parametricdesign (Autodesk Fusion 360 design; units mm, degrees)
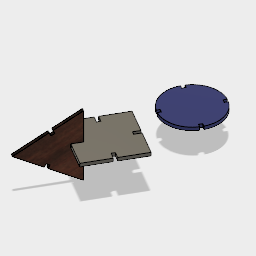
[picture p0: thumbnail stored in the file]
parameter "lengthofobject" = 100
parameter "widthofobject" = 100
parameter "heightofmaterial" = 6
parameter "depthofmaterial" = 12
parameter "radiusofcircle" = 50
sketch "Sketch1" plane through (0, 0, 0) normal (0, 1, 0) x axis (1, 0, 0)
  line L1 (-50, -50) -> (50, -50)
  line L2 (-50, 50) -> (-50, -50)
  line L3 (50, 50) -> (-50, 50)
  line L4 (50, -50) -> (50, 50)
  line L5 (-50, 50) -> (50, -50)
  line L6 (50, 50) -> (-50, -50)
  dimension "d1" distance L1 L3 = 100 (= "lengthofobject")
  dimension "d7" distance L2 L4 = 100 (= "widthofobject")
extrude "Extrude1" new body sketch "Sketch1" profile of L1 L2 L3 L4 along normal blind 6 (= "heightofmaterial")
sketch "Sketch2" plane through (0, 0, 50) normal (0, 0, 1) x axis (1, 0, 0)
  line L1 (50, 0) -> (-50, 0)
  line L2 (50, 6) -> (50, 0)
  line L3 (-50, 6) -> (50, 6)
  line L4 (-50, 0) -> (-50, 6)
  line L5 (-3, 0) -> (3, 0)
  line L6 (-3, 6) -> (-3, 0)
  line L7 (3, 6) -> (-3, 6)
  line L8 (3, 0) -> (3, 6)
  line L9 (-3, 6) -> (3, 0)
  line L10 (3, 6) -> (-3, 0)
  dimension "d10" distance L6 L8 = 6 (= "heightofmaterial")
  dimension "d11" distance L5 L7 = 6 (= "heightofmaterial")
  dimension "d23" distance L4 L6 = 47 (= "widthofobject / 2 - heightofmaterial / 2")
extrude "Extrude2" cut sketch "Sketch2" profile of L1 L3 L5 L6 L7 L8 no distance stored
sketch "Sketch3" plane through (50, 0, 0) normal (1, 0, 0) x axis (0, 0, -1)
  line L1 (50, 0) -> (-50, 0)
  line L2 (50, 6) -> (50, 0)
  line L3 (-50, 6) -> (50, 6)
  line L4 (-50, 0) -> (-50, 6)
  line L5 (-3, 6) -> (3, 6)
  line L6 (-3, 0) -> (-3, 6)
  line L7 (3, 0) -> (-3, 0)
  line L8 (3, 6) -> (3, 0)
  line L9 (-3, 0) -> (3, 6)
  line L10 (3, 0) -> (-3, 6)
  dimension "d14" distance L6 L8 = 6 (= "heightofmaterial")
  dimension "d15" distance L5 L7 = 6 (= "heightofmaterial")
  dimension "d24" distance L4 L6 = 47 (= "widthofobject / 2 - heightofmaterial / 2")
extrude "Extrude3" cut sketch "Sketch3" profile of L1 L3 L5 L6 L7 L8 no distance stored
sketch "Sketch4" plane through (0, 0, -50) normal (0, 0, -1) x axis (-1, 0, 0)
  line L1 (50, 0) -> (-50, 0)
  line L2 (50, 6) -> (50, 0)
  line L3 (-50, 6) -> (50, 6)
  line L4 (-50, 0) -> (-50, 6)
  line L5 (-3, 0) -> (3, 0)
  line L6 (-3, 6) -> (-3, 0)
  line L7 (3, 6) -> (-3, 6)
  line L8 (3, 0) -> (3, 6)
  line L9 (-3, 6) -> (3, 0)
  line L10 (3, 6) -> (-3, 0)
  dimension "d18" distance L6 L8 = 6 (= "heightofmaterial")
  dimension "d19" distance L5 L7 = 6 (= "heightofmaterial")
  dimension "d20" distance L4 L6 = 47 (= "widthofobject / 2 - heightofmaterial / 2")
extrude "Extrude4" cut sketch "Sketch4" profile of L1 L3 L5 L6 L7 L8 no distance stored
sketch "Sketch5" plane through (-50, 0, 0) normal (-1, 0, 0) x axis (0, 0, 1)
  line L1 (50, 0) -> (-50, 0)
  line L2 (50, 6) -> (50, 0)
  line L3 (-50, 6) -> (50, 6)
  line L4 (-50, 0) -> (-50, 6)
  line L5 (-3, 0) -> (3, 0)
  line L6 (-3, 6) -> (-3, 0)
  line L7 (3, 6) -> (-3, 6)
  line L8 (3, 0) -> (3, 6)
  line L9 (-3, 6) -> (3, 0)
  line L10 (3, 6) -> (-3, 0)
  point P1 (0, 0)
  dimension "d25" distance P1 L7 = 6 (= "heightofmaterial")
  dimension "d26" distance L6 L8 = 6 (= "heightofmaterial")
  dimension "d27" distance L4 L6 = 47 (= "widthofobject / 2 - heightofmaterial / 2")
extrude "Extrude5" cut sketch "Sketch5" profile of L1 L3 L5 L6 L7 L8 no distance stored
sketch "Sketch6" plane through (0, 0, 0) normal (0, 1, 0) x axis (1, 0, 0)
  circle C1 centre (200, 0) radius 50
  dimension "d30" diameter C1 = 100 (= "radiusofcircle * 2")
extrude "Extrude6" sketch "Sketch6" blind 6 (= "heightofmaterial")
sketch "Sketch7" plane through (0, 6, 0) normal (0, 1, 0) x axis (-1, 0, 0)
  line L1 (-197, 56) -> (-203, 56)
  line L2 (-197, 44) -> (-197, 56)
  line L3 (-203, 44) -> (-197, 44)
  line L4 (-203, 56) -> (-203, 44)
  line L5 (-197, 44) -> (-203, 56)
  line L6 (-203, 44) -> (-197, 56)
  circle C1 centre (-200, 0) radius 50
  point P2 (-200, 0)
  dimension "d33" distance P2 L3 = 44 (= "radiusofcircle - depthofmaterial / 2")
  dimension "d34" distance L2 L4 = 6 (= "heightofmaterial")
  dimension "d35" distance L1 L3 = 12 (= "depthofmaterial")
extrude "Extrude7" sketch "Sketch7" profile of C1 L2 L3 L4 no distance stored
sketch "Sketch8" plane through (0, 6, 0) normal (0, 1, 0) x axis (-1, 0, 0)
  line L1 (-203, 49.9099) -> (-203, 44)
  line L2 (-197, 44) -> (-197, 49.9099)
  line L3 (-203, 44) -> (-197, 44)
  line L4 (-244, 3) -> (-256, 3)
  line L5 (-244, -3) -> (-244, 3)
  line L6 (-256, -3) -> (-244, -3)
  line L7 (-256, 3) -> (-256, -3)
  line L8 (-244, -3) -> (-256, 3)
  line L9 (-256, -3) -> (-244, 3)
  arc A1 centre (-200, 0) radius 50 clockwise from (-197, 49.9099) to (-203, 49.9099)
  point P5 (-200, 0)
  dimension "d38" distance L5 L7 = 12 (= "depthofmaterial")
  dimension "d39" distance L4 L6 = 6 (= "heightofmaterial")
  dimension "d40" distance P5 L5 = 44 (= "radiusofcircle - depthofmaterial / 2")
extrude "Extrude8" cut sketch "Sketch8" profile of A1 L4 L5 L6 no distance stored
sketch "Sketch9" plane through (0, 6, 0) normal (0, 1, 0) x axis (-1, 0, 0)
  line L1 (-244, 3) -> (-249.9099, 3)
  line L2 (-244, -3) -> (-244, 3)
  line L3 (-249.9099, -3) -> (-244, -3)
  line L4 (-197, 44) -> (-197, 49.9099)
  line L5 (-203, 44) -> (-197, 44)
  line L6 (-203, 49.9099) -> (-203, 44)
  line L7 (-197, -44) -> (-203, -44)
  line L8 (-197, -56) -> (-197, -44)
  line L9 (-203, -56) -> (-197, -56)
  line L10 (-203, -44) -> (-203, -56)
  line L11 (-197, -56) -> (-203, -44)
  line L12 (-203, -56) -> (-197, -44)
  arc A1 centre (-200, 0) radius 50 clockwise from (-197, 49.9099) to (-249.9099, -3)
  arc A2 centre (-200, 0) radius 50 clockwise from (-249.9099, 3) to (-203, 49.9099)
  point P7 (-200, 0)
  dimension "d43" distance L7 L9 = 12 (= "depthofmaterial")
  dimension "d44" distance P7 L7 = 44 (= "radiusofcircle - depthofmaterial / 2")
  dimension "d45" distance L8 L10 = 6 (= "heightofmaterial")
extrude "Extrude9" sketch "Sketch9" profile of A1 L7 L8 L10 no distance stored
sketch "Sketch10" plane through (0, 6, 0) normal (0, 1, 0) x axis (-1, 0, 0)
  line L1 (-197, -49.9099) -> (-197, -44)
  line L2 (-197, 44) -> (-197, 49.9099)
  line L3 (-203, 44) -> (-197, 44)
  line L4 (-203, 49.9099) -> (-203, 44)
  line L5 (-244, 3) -> (-249.9099, 3)
  line L6 (-244, -3) -> (-244, 3)
  line L7 (-249.9099, -3) -> (-244, -3)
  line L8 (-203, -44) -> (-203, -49.9099)
  line L9 (-197, -44) -> (-203, -44)
  line L10 (-144, 3) -> (-156, 3)
  line L11 (-144, -3) -> (-144, 3)
  line L12 (-156, -3) -> (-144, -3)
  line L13 (-156, 3) -> (-156, -3)
  line L14 (-144, -3) -> (-156, 3)
  line L15 (-156, -3) -> (-144, 3)
  arc A1 centre (-200, 0) radius 50 clockwise from (-197, 49.9099) to (-197, -49.9099)
  arc A2 centre (-200, 0) radius 50 clockwise from (-249.9099, 3) to (-203, 49.9099)
  arc A3 centre (-200, 0) radius 50 clockwise from (-203, -49.9099) to (-249.9099, -3)
  point P5 (-200, 0)
  dimension "d48" distance P5 L13 = 44 (= "radiusofcircle - depthofmaterial / 2")
  dimension "d49" distance L10 L12 = 6 (= "heightofmaterial")
extrude "Extrude10" sketch "Sketch10" profile of A1 L10 L12 L13 no distance stored
sketch "Sketch11" plane through (0, 0, 0) normal (0, 1, 0) x axis (1, 0, 0)
  line L1 (57.735, -220) -> (0, -120)
  line L2 (115.4701, -120) -> (57.735, -220)
  line L3 (0, -120) -> (115.4701, -120)
  point P2 (0, -120)
  point P3 (57.735, -220)
  dimension "d52" distance P2 P3 = 100 (= "lengthofobject")
  dimension "d53" distance P2 L2 = 100 (= "lengthofobject")
extrude "Extrude11" sketch "Sketch11" blind 6 (= "heightofmaterial")
sketch "Sketch12" plane through (0, 6, 0) normal (0, 1, 0) x axis (-1, 0, 0)
  line L1 (0, 120) -> (-115.4701, 120)
  line L2 (-57.735, 220) -> (0, 120)
  line L3 (-115.4701, 120) -> (-57.735, 220)
  line L4 (-89.6025, 164.8038) -> (-86.6025, 170)
  line L5 (-84.4064, 161.8038) -> (-89.6025, 164.8038)
  line L6 (-81.4064, 167) -> (-84.4064, 161.8038)
  line L7 (-86.6025, 170) -> (-81.4064, 167)
  dimension "d56" distance L5 L7 = 6 (= "heightofmaterial")
  dimension "d57" distance L4 L6 = 6 (= "depthofmaterial / 2")
extrude "Extrude12" sketch "Sketch12" profile of L3 L4 L5 L6 L7 no distance stored
sketch "Sketch13" plane through (0, 6, 0) normal (0, 1, 0) x axis (-1, 0, 0)
  line L1 (-89.6025, 164.8038) -> (-84.4064, 161.8038)
  line L2 (-115.4701, 120) -> (-89.6025, 164.8038)
  line L3 (0, 120) -> (-115.4701, 120)
  line L4 (-57.735, 220) -> (0, 120)
  line L5 (-86.6025, 170) -> (-57.735, 220)
  line L6 (-81.4064, 167) -> (-86.6025, 170)
  line L7 (-84.4064, 161.8038) -> (-81.4064, 167)
  line L8 (-59.4701, 126) -> (-65.4701, 126)
  line L9 (-59.4701, 114) -> (-59.4701, 126)
  line L10 (-65.4701, 114) -> (-59.4701, 114)
  line L11 (-65.4701, 126) -> (-65.4701, 114)
  line L12 (-59.4701, 114) -> (-65.4701, 126)
  line L13 (-65.4701, 114) -> (-59.4701, 126)
  point P4 (-115.4701, 120)
  dimension "d60" distance L9 L11 = 6 (= "heightofmaterial")
  dimension "d61" distance P4 L11 = 50 (= "lengthofobject / 2")
  dimension "d62" distance L8 L10 = 12 (= "depthofmaterial")
extrude "Extrude13" sketch "Sketch13" profile of L3 L8 L9 L11 no distance stored
sketch "Sketch14" plane through (0, 6, 0) normal (0, 1, 0) x axis (-1, 0, 0)
  line L1 (-65.4701, 126) -> (-65.4701, 120)
  line L2 (-59.4701, 126) -> (-65.4701, 126)
  line L3 (-59.4701, 120) -> (-59.4701, 126)
  line L4 (0, 120) -> (-59.4701, 120)
  line L5 (-57.735, 220) -> (0, 120)
  line L6 (-86.6025, 170) -> (-57.735, 220)
  line L7 (-81.4064, 167) -> (-86.6025, 170)
  line L8 (-84.4064, 161.8038) -> (-81.4064, 167)
  line L9 (-89.6025, 164.8038) -> (-84.4064, 161.8038)
  line L10 (-115.4701, 120) -> (-89.6025, 164.8038)
  line L11 (-65.4701, 120) -> (-115.4701, 120)
  line L12 (-25.8675, 164.8038) -> (-28.8675, 170)
  line L13 (-31.0637, 161.8038) -> (-25.8675, 164.8038)
  line L14 (-34.0637, 167) -> (-31.0637, 161.8038)
  line L15 (-28.8675, 170) -> (-34.0637, 167)
  dimension "d65" distance L13 L15 = 6 (= "heightofmaterial")
  dimension "d66" distance L12 L14 = 6 (= "depthofmaterial / 2")
extrude "Extrude14" sketch "Sketch14" profile of L5 L12 L13 L14 L15 no distance stored
align "Align1"
align "Align2"
move "Move1"
move "Move2"
move "Move3"
move "Move4"
move "Move5"
sketch "Sketch15" plane through (0, -65.0126, 0) normal (0, 1, 0) x axis (-1, 0, 0)
  line L1 (-240.9709, -10.5559) -> (-238.0159, -5.4377)
  line L2 (-182.0089, 9.5693) -> (-176.8907, 6.6144)
  line L3 (-179.0089, 14.7655) -> (-182.0089, 9.5693)
  line L4 (-173.8907, 11.8105) -> (-179.0089, 14.7655)
  line L5 (-194.0159, 70.7725) -> (-191.0609, 75.8907)
  line L6 (-199.2121, 73.7725) -> (-194.0159, 70.7725)
  line L7 (-196.2571, 78.8907) -> (-199.2121, 73.7725)
  line L8 (-255.2191, 58.7655) -> (-260.3372, 61.7205)
  line L9 (-258.2191, 53.5693) -> (-255.2191, 58.7655)
  line L10 (-263.3372, 56.5243) -> (-258.2191, 53.5693)
  line L11 (-243.2121, -2.4377) -> (-246.167, -7.5559)
  line L12 (-238.0159, -5.4377) -> (-243.2121, -2.4377)
  line L13 (-238.0159, -5.4377) -> (-240.9709, -10.5559)
  line L14 (-243.2121, -2.4377) -> (-238.0159, -5.4377)
  line L15 (-246.167, -7.5559) -> (-243.2121, -2.4377)
  line L16 (-258.2191, 53.5693) -> (-263.3372, 56.5243)
  line L17 (-255.2191, 58.7655) -> (-258.2191, 53.5693)
  line L18 (-260.3372, 61.7205) -> (-255.2191, 58.7655)
  line L19 (-199.2121, 73.7725) -> (-196.2571, 78.8907)
  line L20 (-194.0159, 70.7725) -> (-199.2121, 73.7725)
  line L21 (-191.0609, 75.8907) -> (-194.0159, 70.7725)
  line L22 (-179.0089, 14.7655) -> (-173.8907, 11.8105)
  line L23 (-182.0089, 9.5693) -> (-179.0089, 14.7655)
  line L24 (-176.8907, 6.6144) -> (-182.0089, 9.5693)
  arc A1 centre (-218.614, 34.1674) radius 50 clockwise from (-176.8907, 6.6144) to (-240.9709, -10.5559)
  arc A2 centre (-218.614, 34.1674) radius 50 clockwise from (-191.0609, 75.8907) to (-173.8907, 11.8105)
  arc A3 centre (-218.614, 34.1674) radius 50 clockwise from (-260.3372, 61.7205) to (-196.2571, 78.8907)
  arc A4 centre (-218.614, 34.1674) radius 50 clockwise from (-246.167, -7.5559) to (-263.3372, 56.5243)
  arc A5 centre (-218.614, 34.1674) radius 50 clockwise from (-246.167, -7.5559) to (-263.3372, 56.5243)
  arc A6 centre (-218.614, 34.1674) radius 50 clockwise from (-260.3372, 61.7205) to (-196.2571, 78.8907)
  arc A7 centre (-218.614, 34.1674) radius 50 clockwise from (-191.0609, 75.8907) to (-173.8907, 11.8105)
  arc A8 centre (-218.614, 34.1674) radius 50 clockwise from (-176.8907, 6.6144) to (-240.9709, -10.5559)
sketch "Sketch16" plane through (0, -49, 0) normal (0, 1, 0) x axis (-1, 0, 0)
  line L1 (-182.4013, 216.0718) -> (-176.4013, 226.4641)
  line L2 (-187.5974, 219.0718) -> (-182.4013, 216.0718)
  line L3 (-181.5974, 229.4641) -> (-187.5974, 219.0718)
  line L4 (-222.3006, 252.9641) -> (-181.5974, 229.4641)
  line L5 (-245.8006, 212.2609) -> (-222.3006, 252.9641)
  line L6 (-235.4083, 206.2609) -> (-245.8006, 212.2609)
  line L7 (-238.4083, 201.0648) -> (-235.4083, 206.2609)
  line L8 (-248.8006, 207.0648) -> (-238.4083, 201.0648)
  line L9 (-272.3006, 166.3616) -> (-248.8006, 207.0648)
  line L10 (-231.5974, 142.8616) -> (-272.3006, 166.3616)
  line L11 (-225.5974, 153.2539) -> (-231.5974, 142.8616)
  line L12 (-220.4013, 150.2539) -> (-225.5974, 153.2539)
  line L13 (-226.4013, 139.8616) -> (-220.4013, 150.2539)
  line L14 (-185.6981, 116.3616) -> (-226.4013, 139.8616)
  line L15 (-162.1981, 157.0648) -> (-185.6981, 116.3616)
  line L16 (-172.5904, 163.0648) -> (-162.1981, 157.0648)
  line L17 (-169.5904, 168.2609) -> (-172.5904, 163.0648)
  line L18 (-159.1981, 162.2609) -> (-169.5904, 168.2609)
  line L19 (-135.6981, 202.9641) -> (-159.1981, 162.2609)
  line L20 (-176.4013, 226.4641) -> (-135.6981, 202.9641)
  line L21 (-176.4013, 226.4641) -> (-182.4013, 216.0718)
  line L22 (-135.6981, 202.9641) -> (-176.4013, 226.4641)
  line L23 (-159.1981, 162.2609) -> (-135.6981, 202.9641)
  line L24 (-169.5904, 168.2609) -> (-159.1981, 162.2609)
  line L25 (-172.5904, 163.0648) -> (-169.5904, 168.2609)
  line L26 (-162.1981, 157.0648) -> (-172.5904, 163.0648)
  line L27 (-185.6981, 116.3616) -> (-162.1981, 157.0648)
  line L28 (-226.4013, 139.8616) -> (-185.6981, 116.3616)
  line L29 (-220.4013, 150.2539) -> (-226.4013, 139.8616)
  line L30 (-225.5974, 153.2539) -> (-220.4013, 150.2539)
  line L31 (-231.5974, 142.8616) -> (-225.5974, 153.2539)
  line L32 (-272.3006, 166.3616) -> (-231.5974, 142.8616)
  line L33 (-248.8006, 207.0648) -> (-272.3006, 166.3616)
  line L34 (-238.4083, 201.0648) -> (-248.8006, 207.0648)
  line L35 (-235.4083, 206.2609) -> (-238.4083, 201.0648)
  line L36 (-245.8006, 212.2609) -> (-235.4083, 206.2609)
  line L37 (-222.3006, 252.9641) -> (-245.8006, 212.2609)
  line L38 (-181.5974, 229.4641) -> (-222.3006, 252.9641)
  line L39 (-187.5974, 219.0718) -> (-181.5974, 229.4641)
  line L40 (-182.4013, 216.0718) -> (-187.5974, 219.0718)
  line L41 (-59.7829, 74.2298) -> (-64.9791, 71.2298)
  line L42 (-88.6505, 124.2298) -> (-59.7829, 74.2298)
  line L43 (-117.518, 74.2298) -> (-88.6505, 124.2298)
  line L44 (-112.3218, 71.2298) -> (-117.518, 74.2298)
  line L45 (-115.3218, 66.0336) -> (-112.3218, 71.2298)
  line L46 (-120.518, 69.0336) -> (-115.3218, 66.0336)
  line L47 (-146.3855, 24.2298) -> (-120.518, 69.0336)
  line L48 (-96.3855, 24.2298) -> (-146.3855, 24.2298)
  line L49 (-96.3855, 30.2298) -> (-96.3855, 24.2298)
  line L50 (-90.3855, 30.2298) -> (-96.3855, 30.2298)
  line L51 (-90.3855, 24.2298) -> (-90.3855, 30.2298)
  line L52 (-30.9154, 24.2298) -> (-90.3855, 24.2298)
  line L53 (-56.7829, 69.0336) -> (-30.9154, 24.2298)
  line L54 (-61.9791, 66.0336) -> (-56.7829, 69.0336)
  line L55 (-64.9791, 71.2298) -> (-61.9791, 66.0336)
sketch "Sketch17" plane through (0, -63.8737, 0) normal (0, 1, 0) x axis (-1, 0, 0)
  line L1 (-59.7829, 74.2298) -> (-64.9791, 71.2298)
  line L2 (-88.6505, 124.2298) -> (-59.7829, 74.2298)
  line L3 (-117.518, 74.2298) -> (-88.6505, 124.2298)
  line L4 (-112.3218, 71.2298) -> (-117.518, 74.2298)
  line L5 (-115.3218, 66.0336) -> (-112.3218, 71.2298)
  line L6 (-120.518, 69.0336) -> (-115.3218, 66.0336)
  line L7 (-146.3855, 24.2298) -> (-120.518, 69.0336)
  line L8 (-96.3855, 24.2298) -> (-146.3855, 24.2298)
  line L9 (-96.3855, 30.2298) -> (-96.3855, 24.2298)
  line L10 (-90.3855, 30.2298) -> (-96.3855, 30.2298)
  line L11 (-90.3855, 24.2298) -> (-90.3855, 30.2298)
  line L12 (-30.9154, 24.2298) -> (-90.3855, 24.2298)
  line L13 (-56.7829, 69.0336) -> (-30.9154, 24.2298)
  line L14 (-61.9791, 66.0336) -> (-56.7829, 69.0336)
  line L15 (-64.9791, 71.2298) -> (-61.9791, 66.0336)
extrude "Extrude15" sketch "Sketch2" profile of L1 L3 L5 L6 L7 L8 no distance stored
extrude "Extrude16" sketch "Sketch2" profile of L1 L3 L5 L6 L7 L8 blind -6 (= "-depthofmaterial / 2")
extrude "Extrude17" sketch "Sketch3" profile of L1 L3 L5 L6 L7 L8 blind -6 (= "-depthofmaterial / 2")
extrude "Extrude18" sketch "Sketch4" profile of L1 L3 L5 L6 L7 L8 blind -6 (= "-depthofmaterial / 2")
extrude "Extrude19" sketch "Sketch5" profile of L1 L3 L5 L6 L7 L8 blind -6 (= "-depthofmaterial / 2")
extrude "Extrude20" sketch "Sketch2" profile of L1 L3 L5 L6 L7 L8 no distance stored
align "Align3"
